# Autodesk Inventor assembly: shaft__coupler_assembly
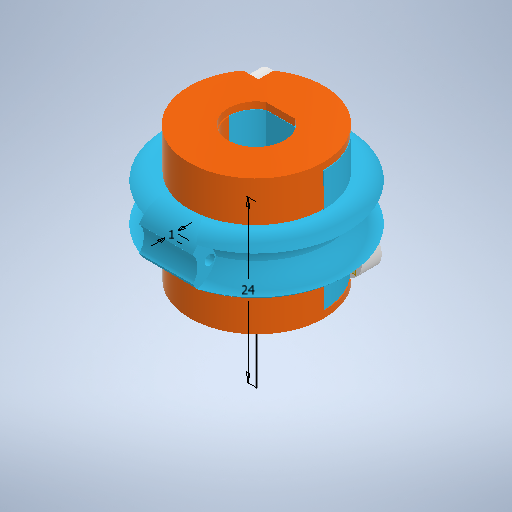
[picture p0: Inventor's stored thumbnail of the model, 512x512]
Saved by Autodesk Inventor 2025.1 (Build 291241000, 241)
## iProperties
Created: 2025-03
Part Number: shaft__coupler_assembly
Document SubType Name: Assembly
Designer: Usuario
Author: Usuario
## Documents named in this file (4)
- C:\Users\Usuario\Desktop\EXOGLOVE\actuacion\shaft__coupler_assembly.iam
- C:\Users\Usuario\Desktop\EXOGLOVE\actuacion\shaft_coupler_p1.ipt
- C:\Users\Usuario\Desktop\EXOGLOVE\actuacion\shaft_coupler_p2.ipt
- C:\Users\Usuario\Desktop\EXOGLOVE\actuacion\tornillo_M3.ipt
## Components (5 placed, 3 different names)
1. shaft_coupler_p1:1 — Coincidencia:1, Coincidencia:2
2. shaft_coupler_p1:2 — Coincidencia:3, Coincidencia:4
3. shaft_coupler_p2:1 — Coincidencia:1, Coincidencia:2, Coincidencia:3, Coincidencia:4, Coincidencia:5, Coincidencia:6
4. tornillo_M3:1 — Coincidencia:6
5. tornillo_M3:2 — Coincidencia:5
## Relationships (6: Mate 6)
- Coincidencia:1 [Mate]: shaft_coupler_p1:1 ↔ shaft_coupler_p2:1
- Coincidencia:2 [Mate]: shaft_coupler_p1:1 ↔ shaft_coupler_p2:1
- Coincidencia:3 [Mate]: shaft_coupler_p1:2 ↔ shaft_coupler_p2:1
- Coincidencia:4 [Mate]: shaft_coupler_p1:2 ↔ shaft_coupler_p2:1
- Coincidencia:5 [Mate]: shaft_coupler_p2:1 ↔ tornillo_M3:2
- Coincidencia:6 [Mate]: shaft_coupler_p2:1 ↔ tornillo_M3:1
